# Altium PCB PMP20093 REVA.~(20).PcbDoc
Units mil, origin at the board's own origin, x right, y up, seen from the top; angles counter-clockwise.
Board outline 2600 x 2600 mil, 4 copper layers (Top Layer, Signal Layer 1, Signal Layer 2, Bottom Layer), stack 85.4 mil thick; 58 components, 27 nets, 183 pads, 90 vias.
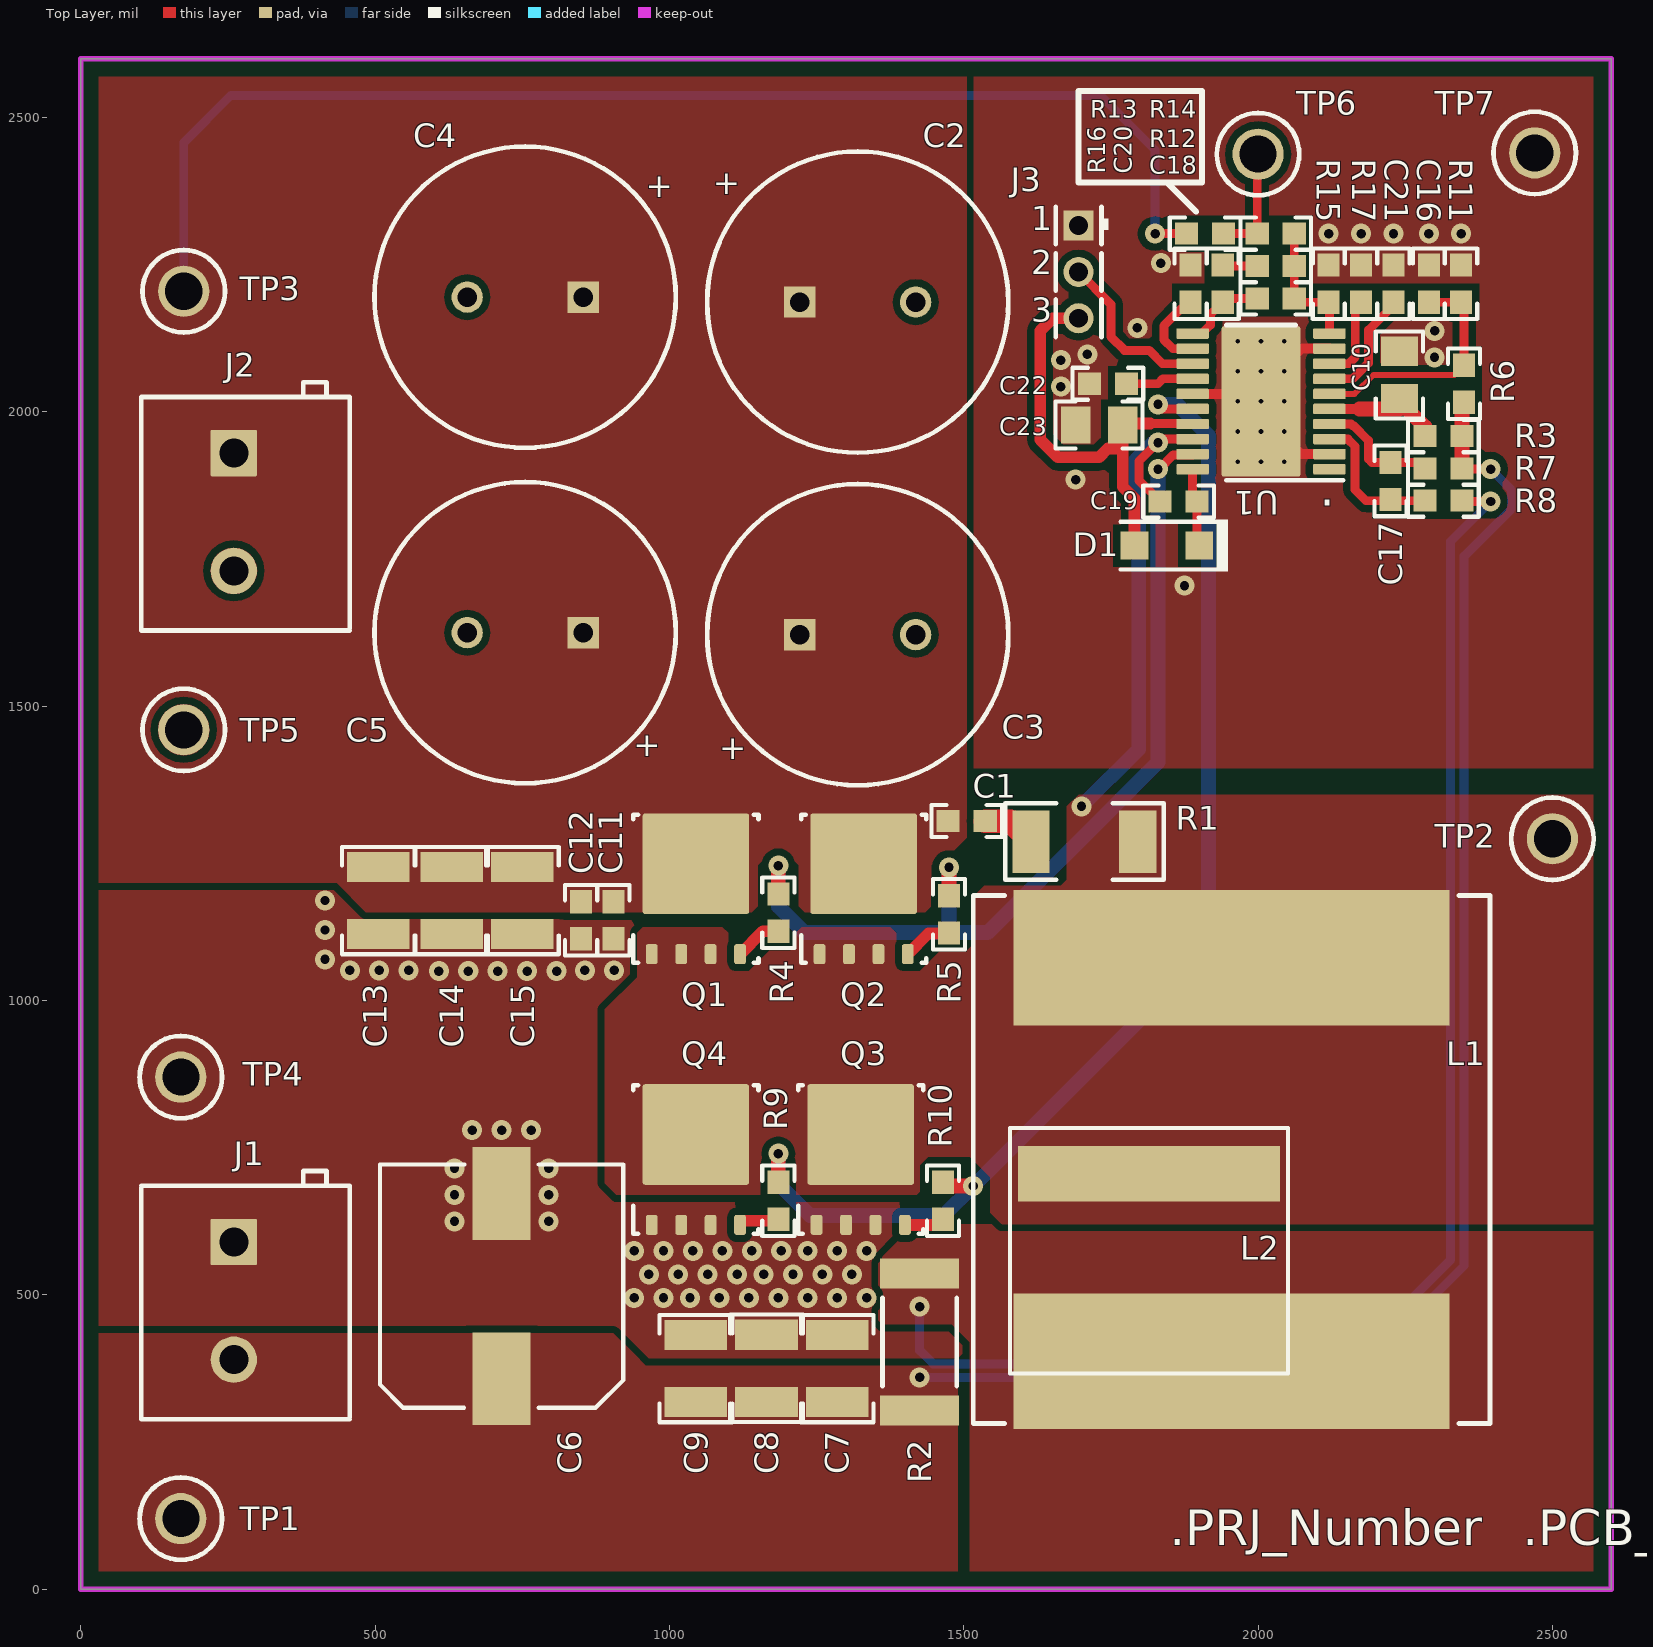
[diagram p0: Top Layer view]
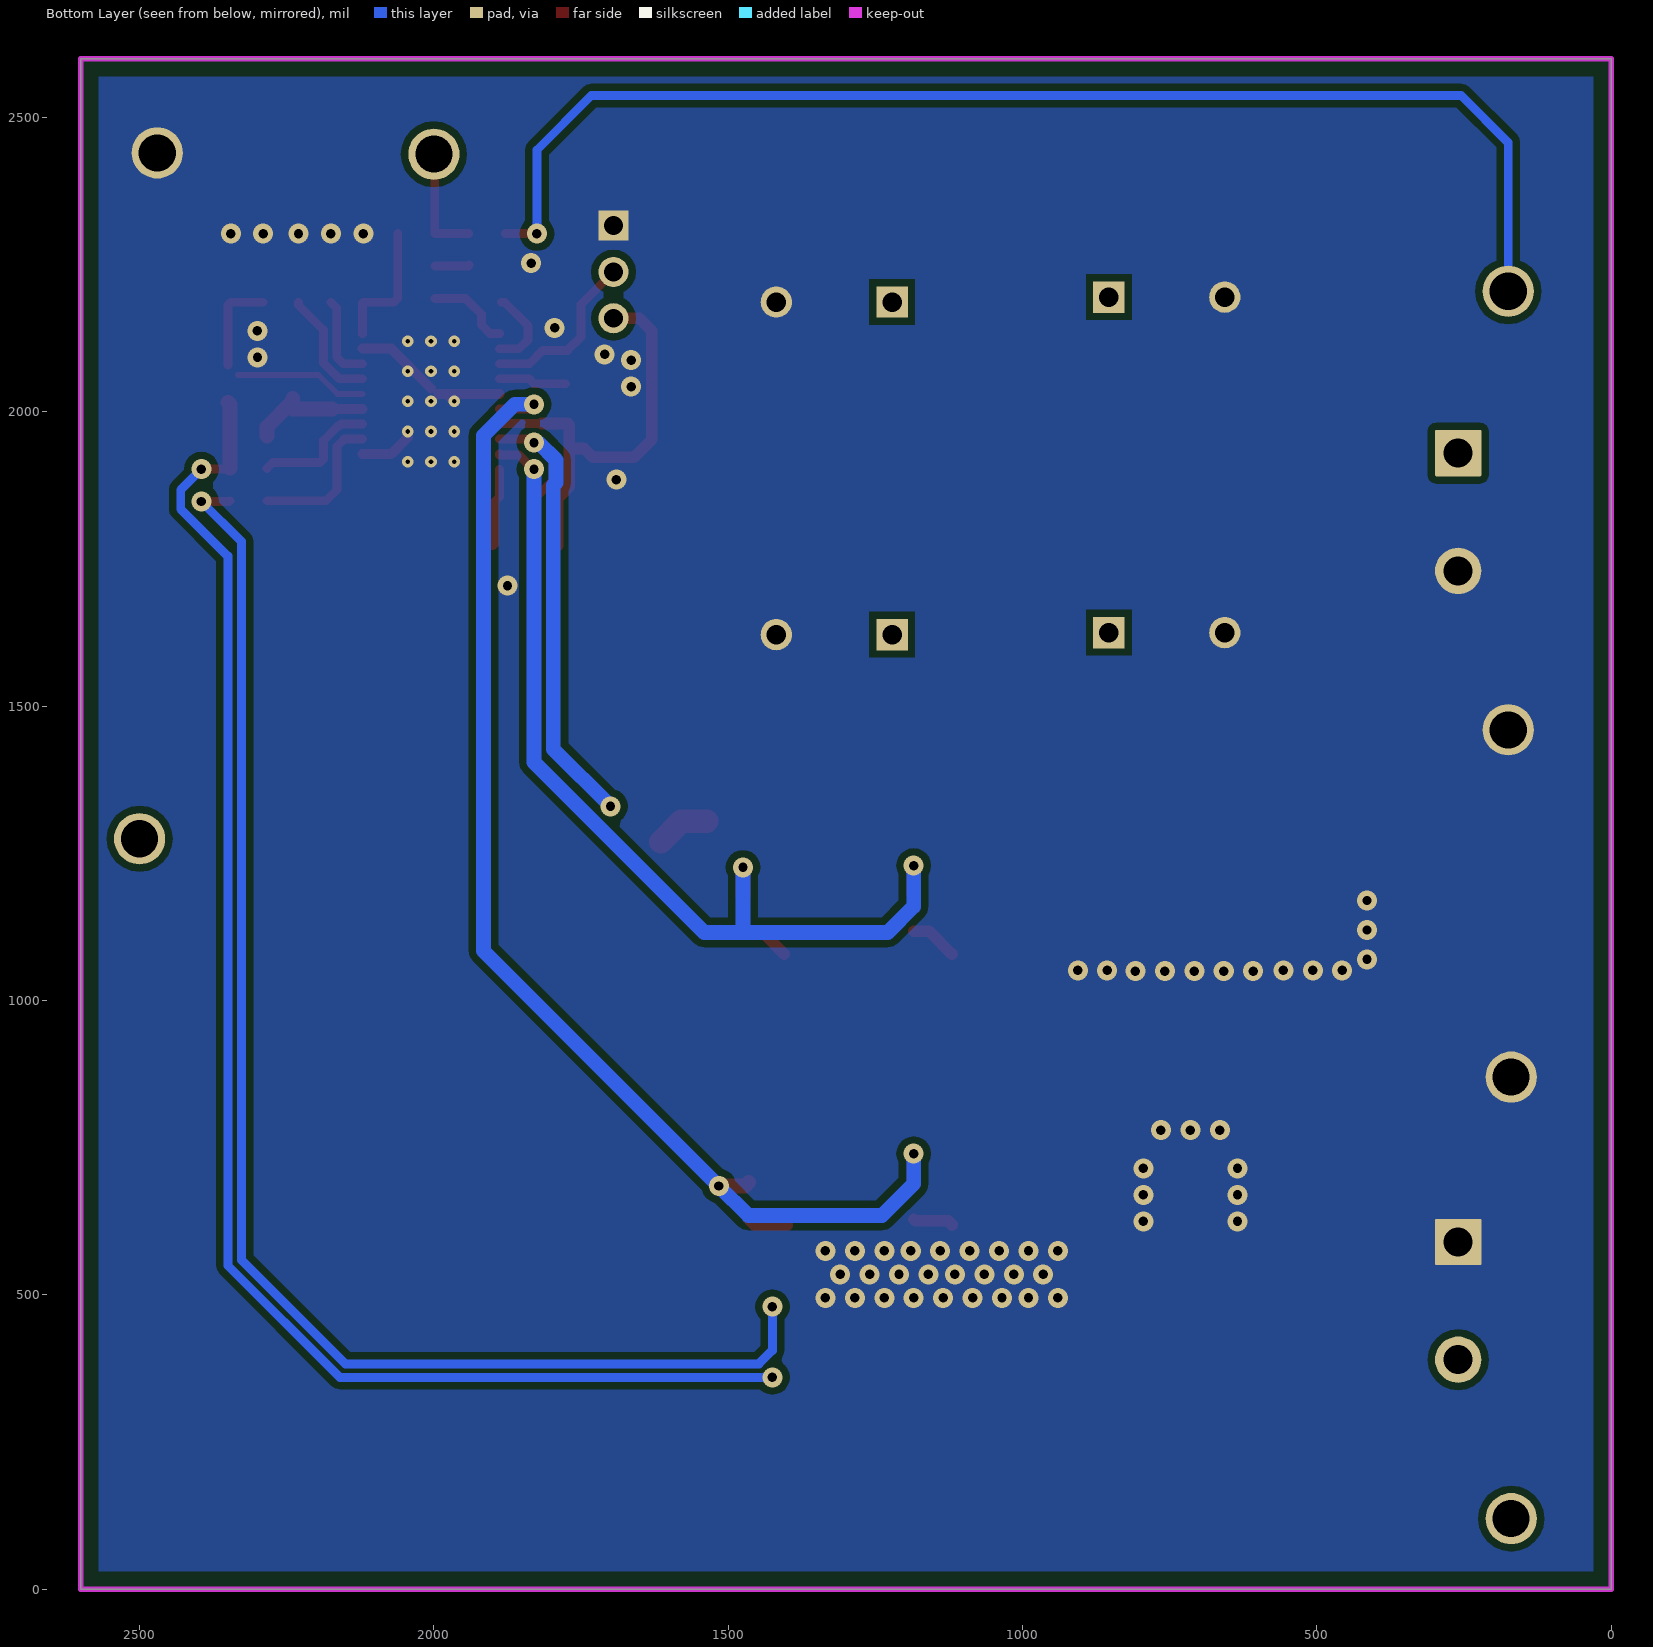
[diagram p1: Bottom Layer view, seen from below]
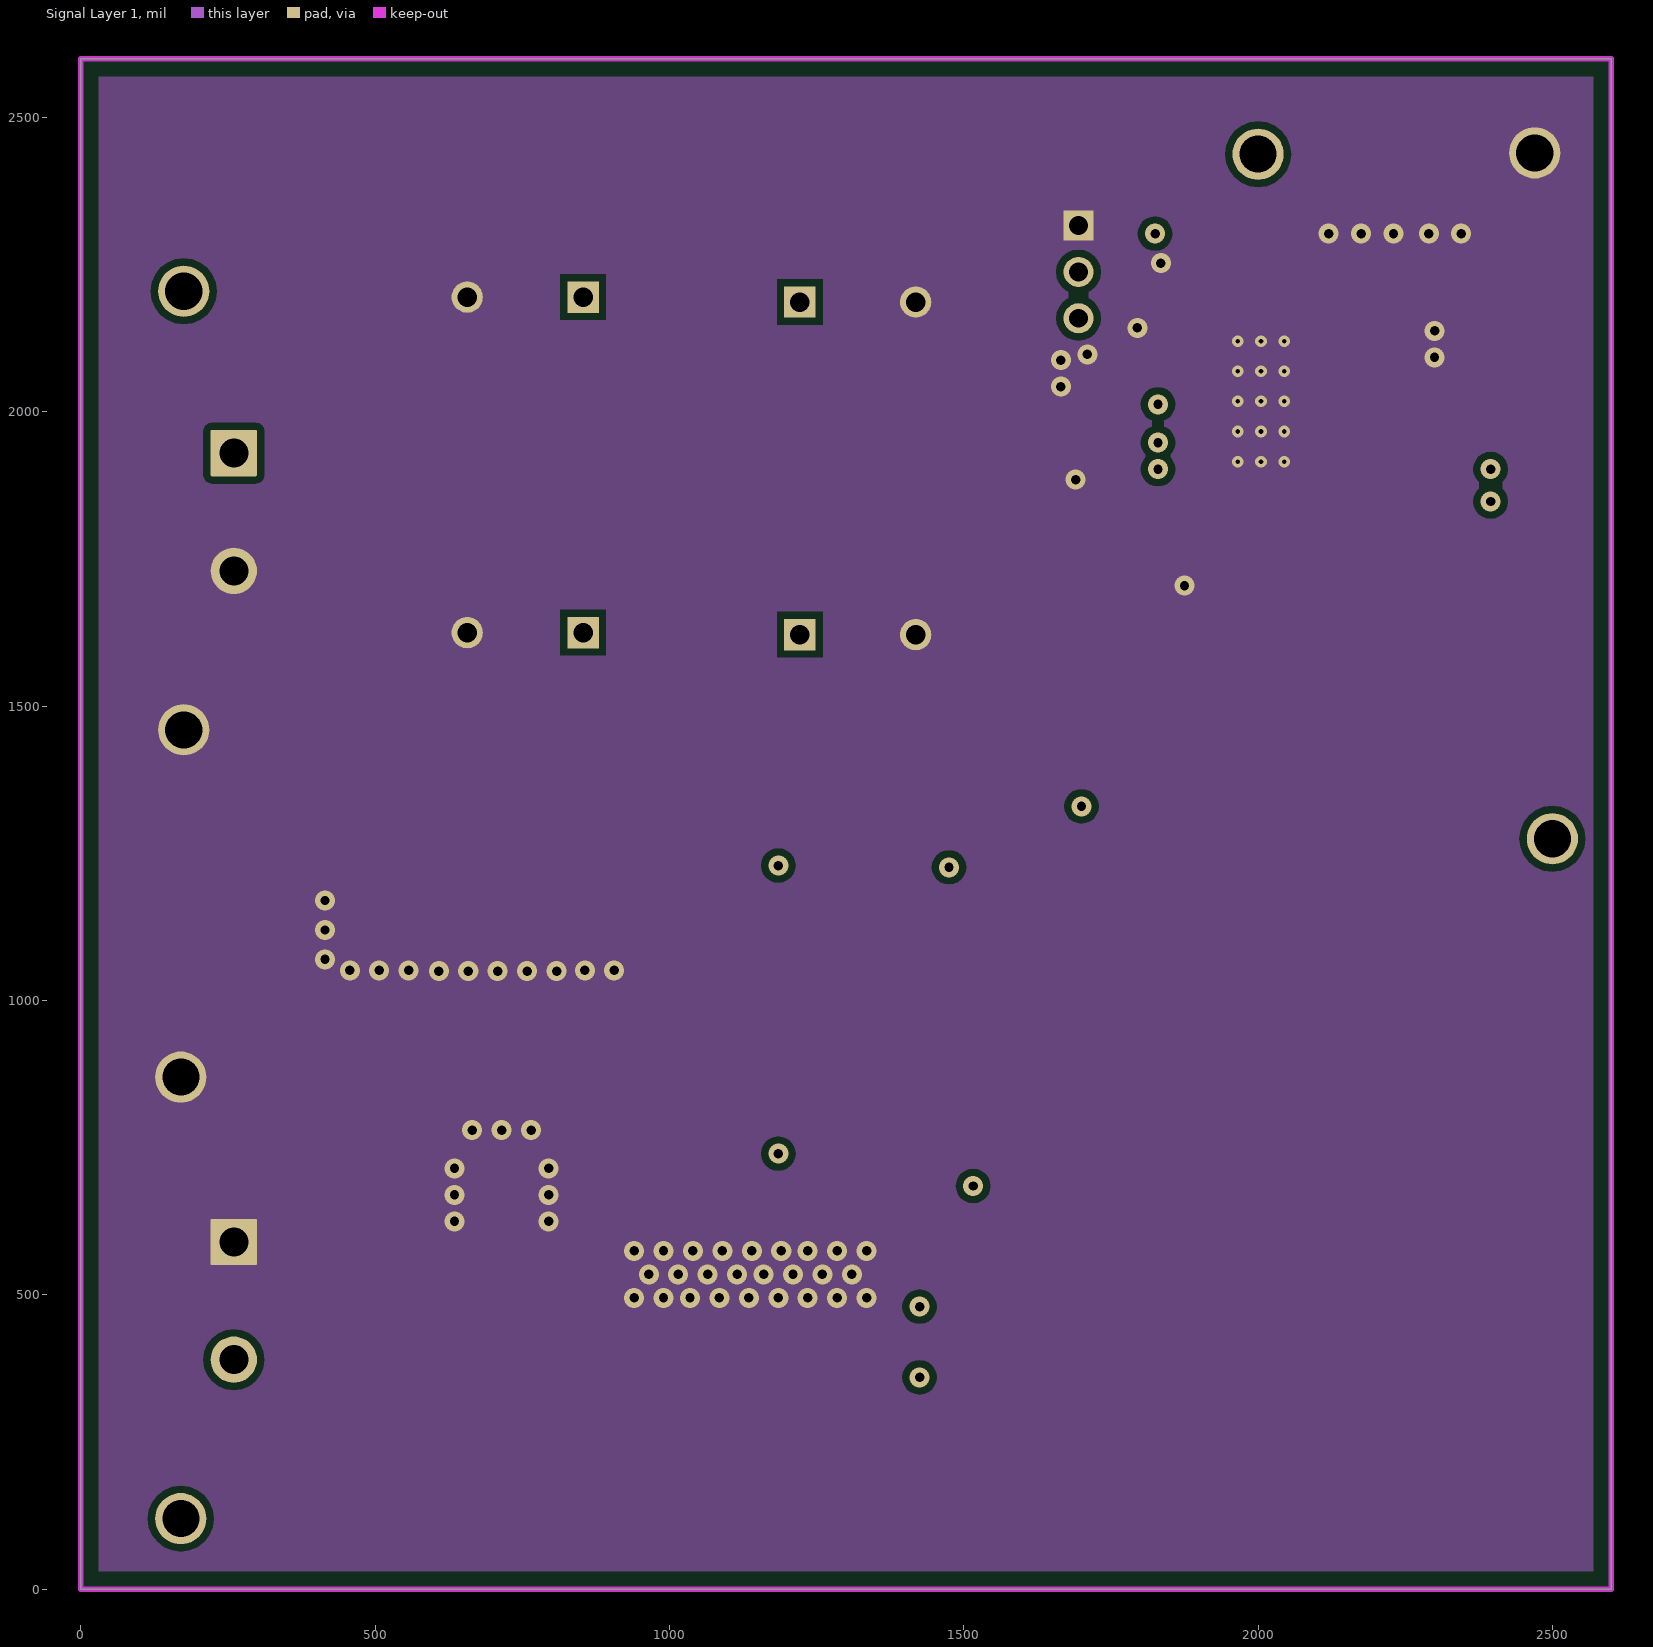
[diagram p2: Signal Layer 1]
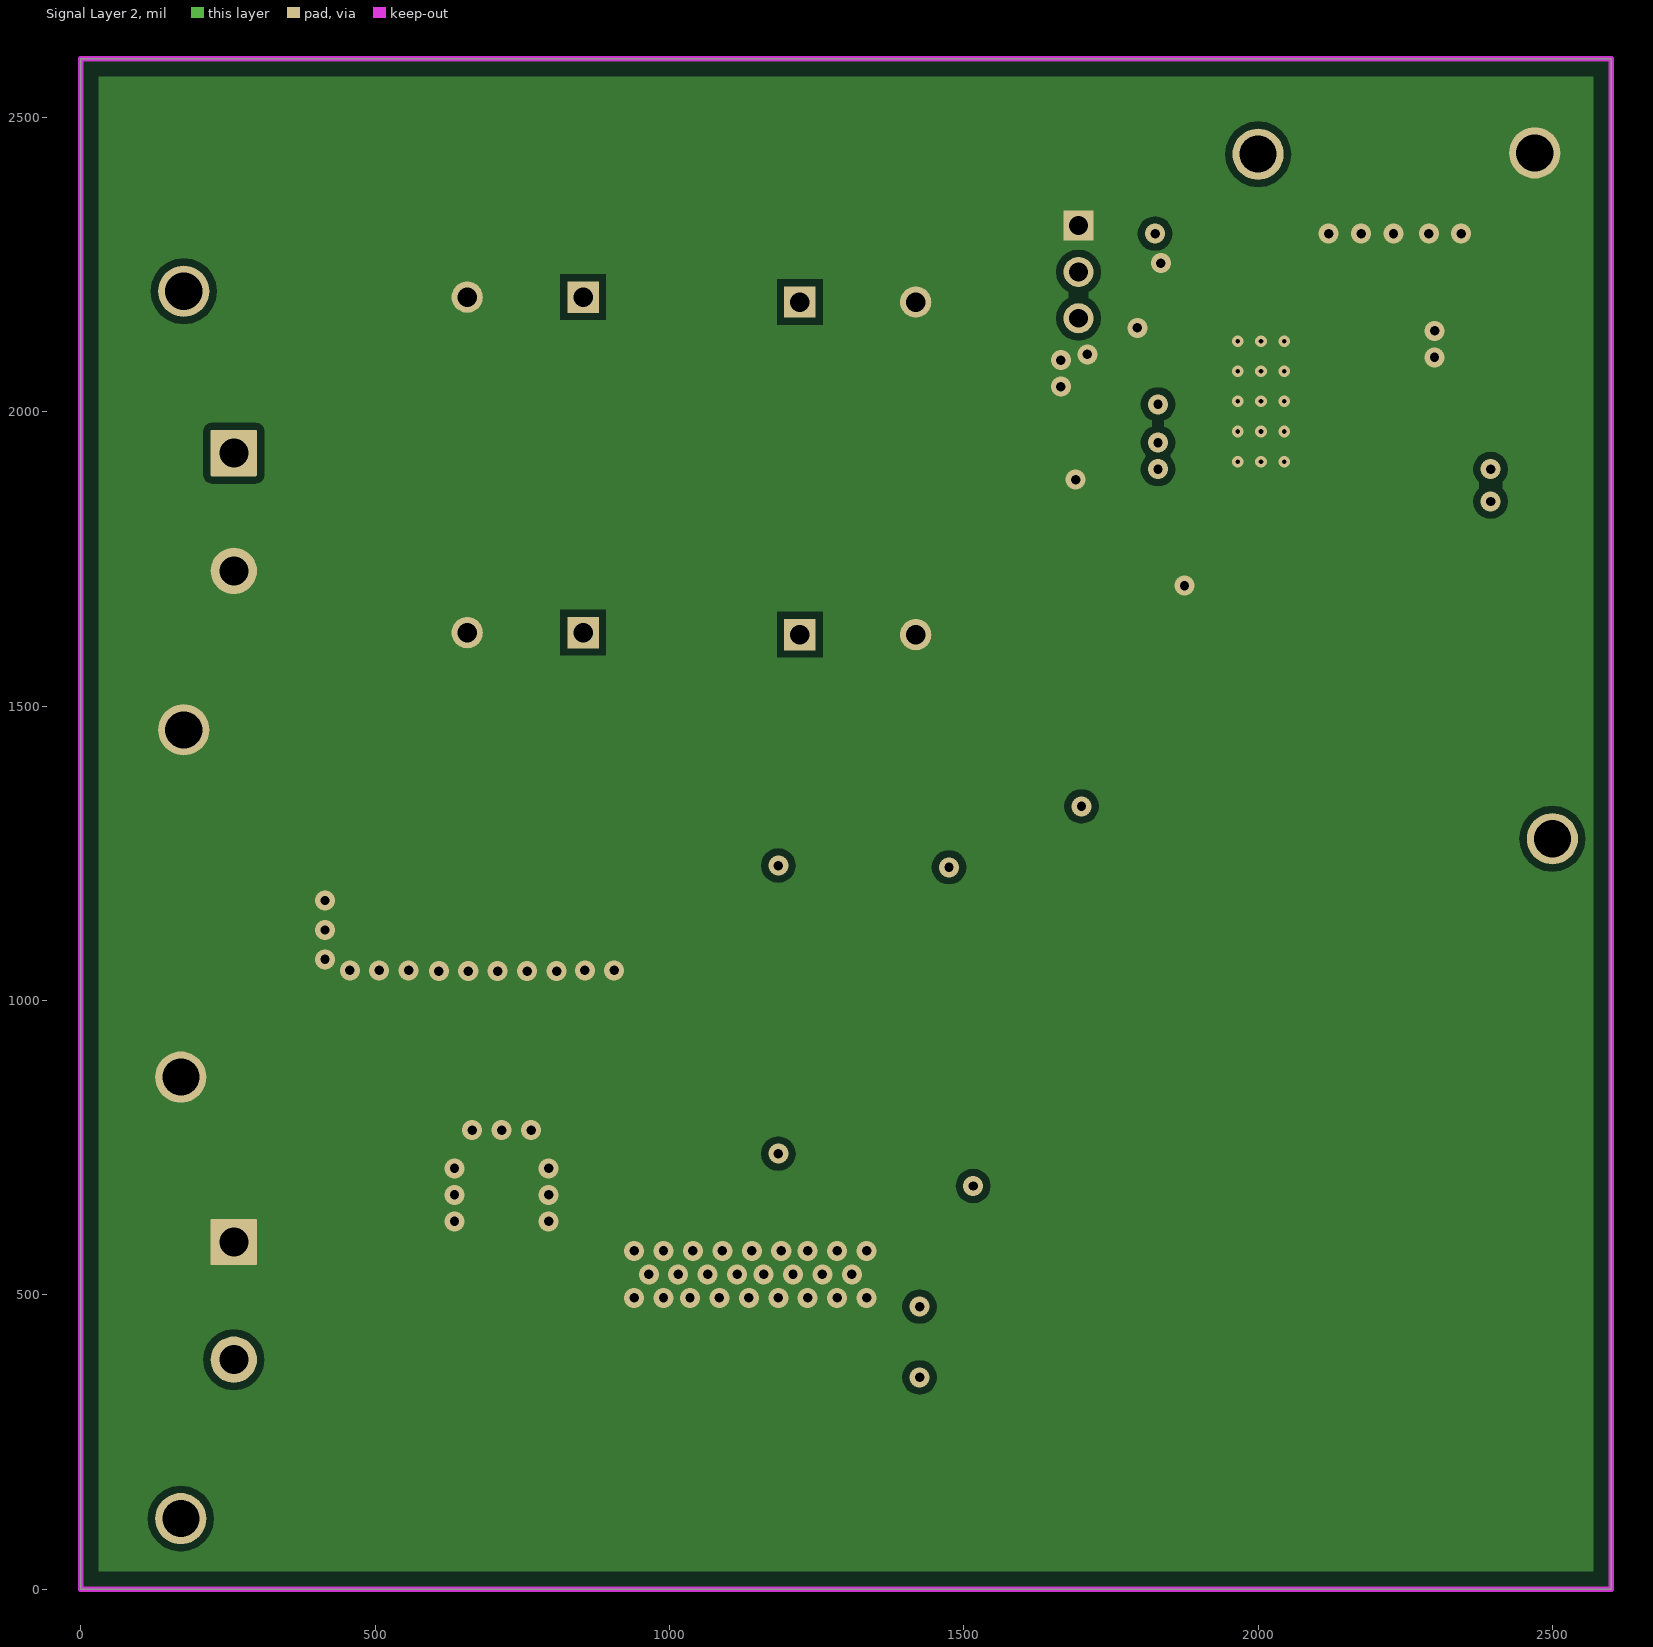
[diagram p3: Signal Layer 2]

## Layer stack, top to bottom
Top Solder: solder mask 0.4, Solder Resist, Dk 3.5
Top Layer: signal copper 2.8
Dielectric1: core 59.2, FR-4, Dk 4.8
Signal Layer 1: signal copper 2.8
Dielectric 3: prepreg 5, Dk 4.2
Signal Layer 2: signal copper 2.8
Dielectric 2: core 10, Dk 4.2
Bottom Layer: signal copper 2.8
Bottom Solder: solder mask 0.4, Solder Resist, Dk 3.5

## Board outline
0,0 2600,0 2600,2600 0,2600

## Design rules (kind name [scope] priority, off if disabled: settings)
AcuteAngle [All] p1: minimum=4.50000000000000E+0001 checktracksonly=FALSE
AssemblyTestPointUsage [All] p1: valid=2
Clearance Clearance_Keepouts [((IsTrack Or IsArc) And Not InPoly) And IsFree and IsKeepOut vs ((IsTrack Or IsArc) And Not InPoly) And IsFree and IsKeepOut] p1: gap=0
Clearance Clearance_BoardEdge_MountingHoles [OnCopper and InComponentClass('Mounting Holes') vs IsKeepOut] p2: gap=40
Clearance Clearance_BoardEdge_Poly [OnCopper and InPoly vs IsKeepOut] p3: gap=25
Clearance Clearance_BoardEdge [OnCopper and Not InComponentClass('Logo') and not InComponentClass('FiducialMark') and not InRegion(1000,500,4000,800) and Not IsKeepout vs IsKeepOut] p4: gap=50
Clearance Clearance_Poly [InPolygon] p5: gap=12
Clearance [All] p6: gap=7.87
ComponentClearance ComponentClearance_MountingHoles_FiducialMarks [InComponentClass('Mounting Holes') vs InComponentClass('FiducialMark')] p1: gap=50 collisioncheckmode=3 verticalgap=10 showdistances=FALSE
ComponentClearance ComponentClearance_Shunt [InComponentClass('Header') vs InComponentClass('Shunt')] p2: gap=0 collisioncheckmode=3 verticalgap=0 showdistances=FALSE
ComponentClearance ComponentClearance_Logo [InComponentClass('Logo')] p3: gap=50 collisioncheckmode=3 verticalgap=10 showdistances=FALSE
ComponentClearance ComponentClearance_ScrewToNut [(HasFootprint('NY PMS 440 0025 PH')) vs (HasFootprint('Keystone_1902C'))] p4: gap=5 collisioncheckmode=3 verticalgap=10 showdistances=FALSE
ComponentClearance ComponentClearance_MountingHoles [InComponentClass('Mounting Holes')] p5: gap=250 collisioncheckmode=3 verticalgap=100000 showdistances=FALSE
ComponentClearance ComponentClearance_SmallPassives [HasFootprint('0201*') or HasFootprint('0402*') or HasFootprint('0508') or HasFootprint('0603*') or HasFootprint('0612') or HasFootprint('0805*') or HasFootprint('0815*') or HasFootprint('0830*') or HasFootprint('1206*') or HasFootprint('1210*') or HasFootprint('1808*') or HasFootprint('1812*') or HasFootprint('1825*') or HasFootprint('2010*') or HasFootprint('2220*') or HasFootprint('2225*') or HasFootprint('2512*') or HasFootprint('2728*') or HasFootprint('3518*') vs HasFootprint('0201*') or HasFootprint('0402*') or HasFootprint('0508') or HasFootprint('0603*') or HasFootprint('0612') or HasFootprint('0805*') or HasFootprint('0815*') or HasFootprint('0830*') or HasFootprint('1206*') or HasFootprint('1210*') or HasFootprint('1808*') or HasFootprint('1812*') or HasFootprint('1825*') or HasFootprint('2010*') or HasFootprint('2220*') or HasFootprint('2225*') or HasFootprint('2512*') or HasFootprint('2728*') or HasFootprint('3518*')] p6: gap=12 collisioncheckmode=3 verticalgap=10 showdistances=FALSE
ComponentClearance ComponentClearance_THtoSMT [IsThruComponent vs IsSMTComponent] p7: gap=50 collisioncheckmode=3 verticalgap=30 showdistances=FALSE
ComponentClearance ComponentClearance_THtoTH [IsThruComponent vs IsThruComponent] p8: gap=50 collisioncheckmode=3 verticalgap=30 showdistances=FALSE
ComponentClearance [All] p9: gap=20 collisioncheckmode=3 verticalgap=10 showdistances=FALSE
DiffPairsRouting [All] p1: maxlimit=100 minlimit=10 mostfreqgap=10 toplayer_minwidth=15 toplayer_maxwidth=15 toplayer_prefwidth=15 midlayer1_minwidth=15 midlayer1_maxwidth=15 midlayer1_prefwidth=15 midlayer2_minwidth=15 midlayer2_maxwidth=15 midlayer2_prefwidth=15 bottomlayer_minwidth=15 bottomlayer_maxwidth=15 bottomlayer_prefwidth=15 maxuncoupledlength=1000
FabricationTestPointUsage TestPointUsage [All] p1: valid=2 allowmultiple=FALSE
FabricationTestpoint Testpoint [All] p1: side=3 testpointundercomponent=TRUE minsize=40 maxsize=100 preferedsize=60 minholesize=0 maxholesize=40 preferedholesize=32 testpointgrid=1 allowsidetop=TRUE allowsidebottom=TRUE usegrid=TRUE gridtolerance=0.01
FanoutControl Fanout_LCC [IsLCC] p1: bgadir=Out bgaviamode=Centered fanoutstyle=Auto fanoutdirection=Alternating viagrid=1 // Fanout_LCC (Default Rule)
FanoutControl Fanout_BGA [IsBGA] p2: bgadir=Out bgaviamode=Centered fanoutstyle=Auto fanoutdirection=Alternating viagrid=1 // Fanout_BGA (Default Rule)
FanoutControl Fanout_Default [All] p4: bgadir=Out bgaviamode=Centered fanoutstyle=Auto fanoutdirection=Alternating viagrid=1 // Fanout_Default (Default Rule)
FanoutControl Fanout_Small [(CompPinCount < 5)] p5: bgadir=Out bgaviamode=Centered fanoutstyle=Auto fanoutdirection=OutThenIn viagrid=1 // Fanout_Small (Default Rule)
HoleSize [All] p1: absolutevalues=TRUE maxlimit=251 minlimit=8 maxpercent=80.000 minpercent=20.000
MinimumAnnularRing MinimumAnnularRing_ThermalPadVias [IsVia and InAnyComponent] p1: minimumring=5.91
MinimumAnnularRing [All] p2: minimumring=9
MinimumSolderMaskSliver MinimumSolderMaskSliver_Logo [InComponentClass('Logo') vs InComponentClass('Logo')] p1: minsoldermaskwidth=0.7
MinimumSolderMaskSliver [All] p2: minsoldermaskwidth=3.94
PlaneClearance [All] p1: clearance=12
PlaneConnect [All] p1: planeconnectstyle=Direct reliefexpansion=10 reliefentries=4 reliefconductorwidth=10 reliefairgap=10
PolygonConnect [All] p1: connectstyle=Direct reliefconductorwidth=10 reliefentries=4 polygonreliefangle="90 Angle" airgapwidth=10
RoutingVias ThermalPadVias [IsVia and InAnyComponent] p1: holewidth=7.87 width=19.68 viastyle="Through Hole" minholewidth=7.87 minwidth=19.68 maxholewidth=12.99 maxwidth=23.62
RoutingVias [All] p2: holewidth=16 width=34 viastyle="Through Hole" minholewidth=7.87 minwidth=26 maxholewidth=40 maxwidth=65
SilkToBoardRegionClearance [Not ((IsComment or IsDesignator) And (Hide <> 'False')) and not InRegion(1000,500,4000,800)] p1:
SilkToSilkClearance SilkToSilkClearance_Pb-FreeLogo [(HasFootprint('Pb-Free_Overlay_Medium') OR HasFootprint('Pb-Free_Overlay_Small')) vs (HasFootprint('Pb-Free_Overlay_Medium') OR HasFootprint('Pb-Free_Overlay_Small'))] p1: silktosilkclearance=0
SilkToSilkClearance [All] p2: silktosilkclearance=4
SilkToSolderMaskClearance SilkToComonentPadClearance [IsPad and InAnycomponent] p1: minsilkscreentomaskgap=5 clearancetoexposedcopper=TRUE
SilkToSolderMaskClearance "Silk to Solder Mask Opening" [All] p2: minsilkscreentomaskgap=4 clearancetoexposedcopper=FALSE
SolderMaskExpansion [All] p1: expansion=1.97
Width [All] p1: maxlimit=100 minlimit=6 preferedwidth=10 checkconnectedcopper=TRUE
14 further rules are at their usual default settings.

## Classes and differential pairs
component class Header: J3

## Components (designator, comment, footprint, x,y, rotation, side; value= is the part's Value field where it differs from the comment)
C1 "C1608C0G2A471J" 0603#1 1505,1305 r0 top
C2 "50ZL680MEFC12.5X25" ZL_1250x2500 1320,2186.57 r0 top
C3 "50ZL680MEFC12.5X25" ZL_1250x2500 1320,1621.57 r0 top
C4 "50ZL680MEFC12.5X25" ZL_1250x2500 755,2195 r180 top
C5 "50ZL680MEFC12.5X25" ZL_1250x2500 755,1625 r180 top
C6 "EEHZA1V271P" SM_RADIAL_10BMM 715,515 r90 top
C7 "GRM32ER71H475KA88L" 1210_270 1285,375 r90 top
C8 "" 1210_270 1165,375.31 r90 top
C9 "" 1210_270 1045,375 r90 top
C10 "C2012X7R1H105K125AB" 0805_HV 2240,2062.87 r270 top
C11 "C1608C0G2A471J" 0603#1 905,1136.5 r270 top
C12 "C1608X7R1H104K080AA" 0603#1 850,1136.5 r90 top
C13 "GRM32ER71H475KA88L" 1210_270 505.32,1170 r270 top
C14 "GRM32ER71H475KA88L" 1210_270 630.32,1170 r270 top
C15 "GRM32ER71H475KA88L" 1210_270 750.32,1170 r270 top
C16 "GRM188R71H102KA01D" 0603#1 2290,2217.87 r90 top
C17 "C1608C0G2A471J" 0603#2 2193.7,1816.57 r270 top
C18 "GRM1885C1H680JA01D" 0603#1 2030,2192.87 r0 top
C19 "GRM188R71E474KA12D" 0603#1 1865,1847.87 r0 top
C20 "GRM188R71H333KA61D" 0603#1 1940,2217.87 r90 top
C21 "C1608X7R1E105K080AB" 0603#1 2230,2217.87 r90 top
C22 "GRM188R71E474KA12D" 0603#1 1745,2047.87 r0 top
C23 "GRM21BZ71E106KE15L" 0805_HV 1730,1977.87 r180 top
D1 "PMEG6010CEH" SOD-123F 1845,1772.87 r180 top
J1 "ED120/2DS" On-Shore_ED120_2DS 260,490 r270 top
J2 "ED120/2DS" On-Shore_ED120_2DS 260,1830 r270 top
J3 "PTT-103-01-L-S" Samtec_PTT-103-01-x-S 1695,2237.87 r270 top
L1 "IHLP8787MZER6R8M5A" IHLP8787MZ 1955,730 r90 top
L2 "" XAL1010 1815,575 r90 top
Q1 "" DNK0008A#1 1045,1270 r90 top
Q2 "CSD18532Q5B" DNK0008A#2 1280,1335 r90 top
Q3 "CSD18532Q5B" DNK0008A#3 1325,730 r90 top
Q4 "CSD18532Q5B" DNK0008A#3 1045,730 r90 top
R1 "CRM2010-JW-7R5ELF" 2010 1705,1270 r180 top
R2 "CSNL2512FT2L00" 2512 1425,420 r90 top
R3 "CRCW06033R30JNEA" 0603#1 2315,1959.17 r0 top
R4 "CRCW06030000Z0EA" 0603#1 1185,1149.43 r270 top
R5 "CRCW06030000Z0EA" 0603#1 1475,1146.5 r270 top
R6 "CRCW060349K9FKEA" 0603#1 2349.68,2047.87 r270 top
R7 "CRCW0603100RFKEA" 0603#1 2315,1904.17 r180 top
R8 "CRCW0603100RFKEA" 0603#1 2315,1849.17 r180 top
R9 "CRCW06030000Z0EA" 0603#1 1185,660 r90 top
R10 "CRCW06030000Z0EA" 0603#1 1465,660 r270 top
R11 "CRCW06037K87FKEA" 0603#1 2345,2217.87 r270 top
R12 "CRCW0603158KFKEA" 0603#1 2030,2247.87 r180 top
R13 "CRCW0603100RFKEA" 0603#1 1910,2302.87 r180 top
R14 "CRCW060349K9FKEA" 0603#1 2030,2302.87 r180 top
R15 "CRCW06031K78FKEA" 0603#1 2120,2217.87 r270 top
R16 "CRCW060335K7FKEA" 0603#1 1885,2217.87 r270 top
R17 "CRCW060335K7FKEA" 0603#1 2175,2217.87 r270 top
TP1 "5010" Keystone5010 170,120 r0 top
TP2 "5010" Keystone5010 2500,1275 r0 top
TP3 "5010" Keystone5010 175,2205 r0 top
TP4 "5011" Keystone5011 170,870 r0 top
TP5 "5011" Keystone5011 175,1460 r0 top
TP6 "5010" Keystone5010 2000,2437.87 r180 top
TP7 "5011" Keystone5011 2470,2440 r180 top
U1 "LM5122MHX/NOPB" PWP0020A_N 2005,2017.87 r180 top

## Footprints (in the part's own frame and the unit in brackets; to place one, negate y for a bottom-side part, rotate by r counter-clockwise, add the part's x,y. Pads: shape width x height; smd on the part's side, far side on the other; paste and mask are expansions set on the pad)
0603#1 [mm] "0603 from SM-752 data"
  rect 1x0.95 smd: 1(-0.8,0) 2(0.8,0)
  silkscreen extent -1.52,-0.69 1.52,0.69, body extent -0.87,-0.47 0.87,0.47, height 1
0603#2 [mm] "0603 from SM-752 data"
  rect 1x0.95 smd: 1(-2.484,0.795) 2(-0.884,0.795)
  silkscreen extent -3.21,0.1 -0.16,1.49, body extent -2.56,0.32 -0.81,1.27, height 1
0805_HV [mil] "0805 with 30mil clearance between pads"
  rect 50x63 smd: 1(-40,0) 2(40,0)
  silkscreen extent -74,-40 74,40, body extent -43,-29 43,29, height 57
1210_270 [mm] "1210"
  rect 1.3x2.7 smd: 1(-1.45,0) 2(1.45,0)
  silkscreen extent -2.32,-1.57 2.32,1.57, body extent -1.7,-1.35 1.7,1.35, height 2.7
2010 [mm] "Chip Capacitor, Body 5.08x2.54mm, IPC Medium Density"
  rect 1.6x2.7 smd: 1(-2.3,0) 2(2.3,0)
  silkscreen extent -3.42,-1.65 3.42,1.65, body extent -2.73,-1.45 2.73,1.45, height 1.66
2512 [mm] "Chip Resistor, Body 6.3x3.2mm, IPC Medium Density"
  rect 1.3x3.4 smd: 1(-2.95,0) 2(2.95,0)
  silkscreen extent -1.9,-1.6 1.9,1.6, body extent -3.22,-1.67 3.22,1.67, height 0.71
DNK0008A#1 [mm] "SON, 8-Leads, Body 5x6mm"
  rrect39% 0.86x0.51 smd paste-0.05 mask-0.05: 1(-4.852,1.905) 2(-4.852,0.635) 3(-4.852,-0.635) 4(-4.852,-1.905) 5(0.788,-1.905) 6(0.788,-0.635) 7(0.788,0.635) 8(0.788,1.905)
  rrect8% 1.48x1.27 on Top Paste: 9(-2.212,-1.47) 9(-2.212,0) 9(-2.212,1.47) 9(-0.532,1.47) 9(-0.532,0) 9(-0.532,-1.47)
  rrect5% 4.34x4.6 smd paste-3 mask-0.05: 9(-0.952,0)
  silkscreen extent -5.23,-2.7 1.17,2.7, body extent -5.08,-2.55 1.02,2.55, height 1.06
DNK0008A#2 [mm] "SON, 8-Leads, Body 5x6mm"
  rrect39% 0.86x0.51 smd paste-0.05 mask-0.05: 1(-6.503,0.635) 2(-6.503,-0.635) 3(-6.503,-1.905) 4(-6.503,-3.175) 5(-0.863,-3.175) 6(-0.863,-1.905) 7(-0.863,-0.635) 8(-0.863,0.635)
  rrect8% 1.48x1.27 on Top Paste: 9(-3.863,-2.74) 9(-3.863,-1.27) 9(-3.863,0.2) 9(-2.183,-2.74) 9(-2.183,-1.27) 9(-2.183,0.2)
  rrect5% 4.34x4.6 smd paste-3 mask-0.05: 9(-2.603,-1.27)
  silkscreen extent -6.88,-3.97 -0.48,1.43, body extent -6.73,-3.82 -0.63,1.28, height 1.06
DNK0008A#3 [mm] "SON, 8-Leads, Body 5x6mm"
  rrect39% 0.86x0.51 smd paste-0.05 mask-0.05: 1(-2.82,1.905) 2(-2.82,0.635) 3(-2.82,-0.635) 4(-2.82,-1.905) 5(2.82,-1.905) 6(2.82,-0.635) 7(2.82,0.635) 8(2.82,1.905)
  rrect8% 1.48x1.27 on Top Paste: 9(-0.18,1.47) 9(-0.18,0) 9(-0.18,-1.47) 9(1.5,-1.47) 9(1.5,0) 9(1.5,1.47)
  rrect5% 4.34x4.6 smd paste-3 mask-0.05: 9(1.08,0)
  silkscreen extent -3.2,-2.7 3.2,2.7, body extent -3.05,-2.55 3.05,2.55, height 1.06
IHLP8787MZ [mm] "SMD, 2-Leads, Body 22x22.48mm"
  rect 5.84x18.8 smd: 1(-8.7,0) 2(8.7,0)
  silkscreen extent -11.39,-11.15 11.39,11.15, body extent -11.39,-11.15 11.39,11.15, height 13
Keystone5010 [mil] "Keystone Multipurpose loops"
  round 87 hole 63: 1(0,0)
  silkscreen extent -70,-70 70,70, body extent -63,-63 63,62, height 319
Keystone5011 [mil] "Keystone Multipurpose loops"
  round 87 hole 63: 1(0,0)
  silkscreen extent -70,-70 70,70, body extent -63,-63 63,62, height 319
On-Shore_ED120_2DS [mm] "ONSHORE"
  rrect5% 2x2 hole 1.25: 1(-2.54,0)
  round 2 hole 1.25: 2(2.54,0)
  silkscreen extent -5.6,-4 5.12,5, body extent -5.78,-4 5.08,5, height 13
PWP0020A_N [mm] "TSOP, 20-Leads, Body 6.5x4.4mm, Pitch 0.65mm, Exposed Pad, IPC Medium Density"
  rrect22% 1.4x0.45 smd: 1(-2.95,2.925) 2(-2.95,2.275) 3(-2.95,1.625) 4(-2.95,0.975) 5(-2.95,0.325) 6(-2.95,-0.325) 7(-2.95,-0.975) 8(-2.95,-1.625) 9(-2.95,-2.275) 10(-2.95,-2.925) 11(2.95,-2.925) 12(2.95,-2.275) 13(2.95,-1.625) 14(2.95,-0.975) 15(2.95,-0.325) 16(2.95,0.325) 17(2.95,0.975) 18(2.95,1.625) 19(2.95,2.275) 20(2.95,2.925)
  rrect6% 3.4x6.5 smd paste-2 mask-2: 21(0,0)
  rrect3% 3.15x4.35 on Top Paste: 21(0,0)
  rrect3% 3.15x4.35 on Top Solder: 21(0,0)
  silkscreen extent -3.55,-3.3 1.5,3.4, body extent -3.21,-3.25 3.21,3.25, height 1
Samtec_PTT-103-01-x-S [mm] "Header, 2mm, 3x1, TH"
  rect 1.3x1.3 hole 0.81: 1(-2,0)
  round 1.3 hole 0.81: 2(0,0) 3(2,0)
  silkscreen extent -2.81,-0.99 2.81,1.3, body extent -3,-0.99 3,0.99, height 4.7
SM_RADIAL_10BMM [mm] "Nichicon 10x10"
  rect 4x2.5 smd: 1(-4,0) 2(4,0)
  silkscreen extent -5.25,-5.25 5.25,5.25, body extent -5.25,-5.25 5.25,5.25, height 10.5
SOD-123F [mm] "NXP recommended land pattern"
  rect 1.2x1.2 smd paste-0.05: 1(-1.4,0) 2(1.4,0)
  silkscreen extent -2.64,-1.12 2.01,1.12, body extent -1.8,-0.85 1.8,0.85, height 1.2
XAL1010 [mm] "COILCRAFT"
  rect 2.38x11.31 smd: 1(-3.325,0) 2(3.325,0)
  silkscreen extent -5.3,-6 5.3,6, body extent -5.25,-5.9 5.25,5.9, height 10
ZL_1250x2500 [mm] "TH, 2-Leads, Dia 12.5mm, Lead Spacing 5mm"
  rect 1.35x1.35 hole 0.85: 1(-2.5,0)
  round 1.35 hole 0.85: 2(2.5,0)
  silkscreen extent -6.5,-6.5 6.5,6.5, body extent -6.45,-6.49 6.49,6.49, height 27.01

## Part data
C1 C11 C17: "CAP, CERM, 470 pF, 100 V, +/- 5%, C0G/NP0, 0603"
C2 C3 C4 C5: library part 50ZL560MEFC12.5X25, "CAP, AL, 680 µF, 50 V, +/- 20%, 2.86A, 0.021 ohm, TH"
C6: "CAP, Polymer Hybrid, 270 µF, 35 V, +/- 20%, 20 ohm, 10x10 SMD"
C7 C13 C14 C15: "CAP, CERM, 4.7 µF, 50 V, +/- 10%, X7R, 1210"
C8 C9: library part GRM32ER71H475KA88L, "CAP, CERM, 1210"
C10: "CAP, CERM, 1 µF, 50 V, +/- 10%, X7R, 0805"
C12: "CAP, CERM, 0.1 µF, 50 V, +/- 10%, X7R, 0603"
C16: "CAP, CERM, 1000pF, 50V, +/-10%, X7R, 0603"
C18: "CAP, CERM, 68 pF, 50 V, +/- 5%, C0G/NP0, 0603"
C19 C22: "CAP, CERM, 0.47uF, 25V, +/-10%, X7R, 0603"
C20: "CAP, CERM, 0.033 µF, 50 V, +/- 10%, X7R, 0603"
C21: "CAP, CERM, 1 µF, 25 V, +/- 10%, X7R, 0603"
C23: "CAP, CERM, 10 µF, 25 V, +/- 10%, X7R, 0805"
D1: library part PMEG6010CEH,115, "Diode, Schottky, 60V, 1A, SOD-123F"
J1 J2: "Terminal Block, 5.08 mm, 2x1, Brass, TH"
J3: "Header, 2mm, 3x1, Gold, TH"
L1: library part IHLP8787MZER100M5A, "Inductor, Shielded, 6.8 µH, 36A, 0.00284 ohm, AEC-Q200 Grade 0, SMD"
L2: library part XAL1010-222MEB, "Inductor, SMD, alternate footprint"
Q1: library part CSD18532Q5B, "MOSFET, N-CH, DNP"
Q2 Q3 Q4: "MOSFET, N-CH, 60 V, 172 A, DNK0008A (VSON-CLIP-8)"
R1: "RES, 7.5, 5%, 1 W, 2010"
R2: "RES, 0.002, 1%, 2 W, 2512"
R3: "RES, 3.3 ohm, 5%, 0.1W, 0603"
R4 R5 R9 R10: "RES, 0, 5%, 0.1 W, 0603"
R6 R14: "RES, 49.9k ohm, 1%, 0.1W, 0603"
R7 R8: "RES, 100, 1%, 0.1 W, 0603"
R11: "RES, 7.87 k, 1%, 0.1 W, 0603"
R12: "RES, 158 k, 1%, 0.1 W, 0603"
R13: "RES, 100 ohm, 1%, 0.1W, 0603"
R15: "RES, 1.78 k, 1%, 0.1 W, 0603"
R16 R17: "RES, 35.7 k, 1%, 0.1 W, 0603"
TP1 TP2 TP3 TP6: "Test Point, Multipurpose, Red, TH"
TP4 TP5 TP7: "Test Point, Multipurpose, Black, TH"
U1: "Wide Input Synchronous Boost Controller with Multiple Phase Capability, PWP0020A (TSSOP-20)"

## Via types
v1: diameter 34, hole 16, Top Layer to Bottom Layer, 75 vias
v2: diameter 19.68, hole 7.87, Top Layer to Bottom Layer, 9 vias
v3: diameter 19.68, hole 7.87, Top Layer to Bottom Layer, tented both sides, 6 vias

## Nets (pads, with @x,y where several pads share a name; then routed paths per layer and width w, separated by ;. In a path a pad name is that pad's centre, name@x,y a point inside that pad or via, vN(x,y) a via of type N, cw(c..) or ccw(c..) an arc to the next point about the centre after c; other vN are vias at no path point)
GND: C2.2 C3.2 C4.2 C5.2 C6.2 C7.2 C8.2 C9.2 C10.1 C11.2 C12.1 C13.2 C14.2 C15.2 C16.2 C21.2 C22.1 C23.2 J1.1 J2.2 J3.1 Q3.1 Q3.2 Q3.3 Q4.1 Q4.2 Q4.3 R11.1 R15.1 R16.1 R17.1 TP4.1 TP5.1 TP7.1 U1.2 U1.9 U1.15 U1.21@2005,2017.87 | length 364.2
  Top Layer w17: U1.15 U1.21@1978.43,2030.66 ; v2(1965.63,2017.87) U1.21@1978.43,2030.66 ; U1.21@1992.2,2030.66 U1.21@1978.43,2030.66 ; U1.21@2005,2040 2072.43,2107.43 U1.9 ; v2(2044.37,1966.69) 2044.37,1956.5 2072.57,1928.3 U1.2
  other v1: 940,495 990,495 1035,495 1085,495 1135,495 1185,495 1235,495 1285,495 1335,495 965,535 1015,535 1065,535 1115,535 1160,535 1210,535 1260,535 1310,535 940,575 990,575 1040,575 1090,575 1140,575 1190,575 1235,575 1285,575 1335,575 635,625 795,625 635,670 795,670 635,715 795,715 665,780 715,780 765,780 608.31,1050 658.31,1050 708.31,1050 758.31,1050 808.31,1050 457.04,1051.32 507.04,1051.32 557.04,1051.32 856.3,1051.5 906.3,1051.5 415,1070 415,1120 415,1170 1875,1705 1690,1885 1665,2042.87 1665,2087.87 2299.68,2092.87 1710,2097.87 2300,2137.87 1795,2142.87 1835,2252.87 2120,2302.87 2175,2302.87 2230,2302.87 2290,2302.87 2345,2302.87
  other v2: 1965.63,1966.69 2005,1966.69 2005,2017.87 2044.37,2017.87 1965.63,2069.05 2005,2069.05 2044.37,2069.05
  other v3: 1965.63,1915.5 2005,1915.5 2044.37,1915.5 1965.63,2120.23 2005,2120.23 2044.37,2120.23
NetC1_2: C1.2 R1.2 | length 92.5
  Top Layer w40: C1.2 1579.45,1305 R1.2
NetC6_1: C6.1 C7.1 C8.1 C9.1 J1.2 R2.1 R3.2 R6.2 R7.1 TP1.1 | length 2566.8
  Top Layer w15: R7.1 2347.8,1902.87 v1(2395,1902.87)
  Top Layer w25: R7.1 R3.2 2346.5,2013.18 R6.2
  Bottom Layer w15: v1(1425,360) 2160,360 2350,550 2350,1755 2430,1835 2430,1867.87 v1(2395,1902.87)
NetC10_2: C10.2 R3.1 U1.5 | length 200.6
  Top Layer w17: U1.5 2172.2,2005.07
  Top Layer w25: 2172.2,2005.07 C10.2@2240,2005.07 ; C10.2 2240,2018.55 2283.5,1975.05 R3.1
NetC16_1: C16.1 R6.1 R11.2 U1.6 | length 389.3
  Top Layer w10: U1.6 2163.96,2030.66 2196.16,2062.87 R6.1@2333.19,2062.87
  Top Layer w15: C16.1 R11.2 2349.68,2181.69 R6.1
NetC17_1: C17.1 R7.2 U1.4 | length 211.9
  Top Layer w15: U1.4 2158.38,1979.48 2160.66,1977.2 2161.61,1977.2 2187.56,1951.25 2187.56,1919.99 2193.19,1914.36 C17.1 2273.31,1914.36 R7.2
NetC17_2: C17.2 R8.2 U1.3 | length 249
  Top Layer w15: U1.3 2152.57,1953.89 2164.68,1941.77 2164.68,1867.87 2183.39,1849.17 R8.2
NetC18_1: C18.1 C20.1 U1.11 | length 144.9
  Top Layer w15: U1.11 1904.49,2133.02 1919.07,2147.61 1919.07,2165.44 C20.1 1946.5,2192.87 C18.1
NetC18_2: C18.2 R12.1 R14.1 R15.2 U1.10 | length 223.4
  Top Layer w15: R14.1 R12.1 C18.2 2067.99,2186.37 R15.2 ; U1.10 R15.2@2121.14,2185.23
NetC19_1: C19.1 L1.2 L2.2 Q1.1 Q1.2 Q1.3 Q2.1 Q2.2 Q2.3 Q3.5 Q3.6 Q3.7 Q3.8 Q3.9@1325,772.52 Q4.5 Q4.6 Q4.7 Q4.8 Q4.9@1045,772.52 R1.1 TP2.1 U1.18 | length 870.1
  Top Layer w15: C19.1 1797.63,1883.74 1797.63,1916.28 1829.22,1947.87 v1(1830,1947.87) 1836.02,1953.89 U1.18
  Bottom Layer w25: v1(1700,1330) 1797.13,1427.13 1797.13,1875.13 1792.63,1879.63 1792.63,1918.35 1822.15,1947.87 v1(1830,1947.87)
NetC19_2: C19.2 D1.1 U1.20 | length 134.5
  Top Layer w15: U1.20 1888.86,1855.5 C19.2 1896.5,1776.49 D1.1
NetC20_2: C20.2 R12.2 | length 59.1
  Top Layer w15: C20.2 1941.5,2247.87 R12.2
NetC21_1: C21.1 U1.7 | length 198.4
  Top Layer w15: U1.7 2160.73,2056.25 2187.87,2083.39 2187.87,2139.12 2230,2181.24 C21.1
NetC22_2: C22.2 U1.14 | length 115.8
  Top Layer w15: C22.2 1830,2047.87 1838.39,2056.25 U1.14
NetJ3_2: J3.2 U1.13 | length 290.7
  Top Layer w15: J3.2 1750,2182.87 1750,2127.87 1773.31,2104.56 1815,2104.56 1837.72,2081.84 U1.13
NetL1_1: L1.1 L2.1 R2.2 R8.1 | length 2424.5
  Top Layer w15: R8.1 2347.8,1847.87 v1(2395,1847.87)
  Bottom Layer w15: v1(1425,480) 1425,405.78 1447.91,382.87 2150.53,382.87 2327.13,559.47 2327.13,1779.99 v1(2395,1847.87)
NetQ1_4: Q1.4 R4.2 | length 81.1
  Top Layer w20: Q1.4 1158.96,1117.93 R4.2
NetQ2_4: Q2.4 R5.2 | length 84.9
  Top Layer w20: Q2.4 1440,1113.98 1473.98,1113.98 R5.2
NetQ3_4: Q3.4 R10.2 | length 68.9
  Top Layer w20: Q3.4 1455.47,618.98 R10.2
NetQ4_4: Q4.4 R9.1 | length 69.5
  Top Layer w20: Q4.4 1120,620 1126,626 1182.5,626 R9.1
NetR4_1: R4.1 R5.1 U1.19 | length 1628.5
  Top Layer w15: v1(1830,1902.87) 1832,1902.87 1856.07,1926.94 1888.86,1926.94 U1.19
  Top Layer w25: R4.1 v1(1185,1229.43) ; R5.1 v1(1475,1226.5)
  Bottom Layer w25: v1(1185,1229.43) 1185,1160 1229.3,1115.7 1540.7,1115.7 1830,1405 v1(1830,1902.87) ; 1475,1115.7 v1(1475,1226.5)
NetR9_2: R9.2 R10.1 U1.16 | length 2137.9
  Top Layer w15: v1(1830,2012.87) 1837.8,2005.07 U1.16
  Top Layer w25: R9.2 v1(1185,740) ; R10.1 1471.5,685 v1(1516.02,685)
  Bottom Layer w25: v1(1185,740) 1185,688.7 1238.7,635 1466.02,635 v1(1516.02,685) 1915.87,1084.84 1915.87,1959.87 1862.87,2012.87 v1(1830,2012.87)
NetR13_1: R13.1 R14.2 TP6.1 | length 192.6
  Top Layer w15: R13.1 R14.2 1998.5,2436.37 TP6.1
NetR16_2: R16.2 U1.12 | length 140.2
  Top Layer w15: R16.2 1880.2,2186.37 1840,2146.17 1840,2122.87 1855.43,2107.43 U1.12
NetR17_2: R17.2 U1.8 | length 146.1
  Top Layer w15: U1.8 2153.98,2081.84 2165,2092.87 2165,2176.37 R17.2
VCC: C23.1 D1.2 J3.3 U1.17 | length 751.3
  Top Layer w15: 1816.84,1980.24 1888.86,1980.24 U1.17
  Top Layer w20: J3.3 1651.26,2159.13 1630,2137.87 1630,1952.87 1660,1922.87 1730,1922.87 1745,1937.87 1770,1937.87 ; D1.2 1789.88,1852.98 1770,1872.87 1770,1937.87 ; 1816.84,1980.24 1772.37,1980.24 C23.1 1770,1937.87
VOUT: C1.1 C2.1 C3.1 C4.1 C5.1 C11.1 C12.2 C13.1 C14.1 C15.1 J2.1 Q1.5 Q1.6 Q1.7 Q1.8 Q1.9@1045,1232.52 Q2.5 Q2.6 Q2.7 Q2.8 Q2.9@1330,1232.52 R13.2 TP3.1 | length 2169.6
  Top Layer w15: v1(1825,2302.87) R13.2
  Bottom Layer w15: TP3.1 175,2457.5 255,2537.5 1732.5,2537.5 1825,2445 v1(1825,2302.87)
pads on no net: Q1.9@987.13,1182.91 Q1.9@987.13,1249.06 Q1.9@1045,1182.91 Q1.9@1045,1249.06 Q1.9@1102.87,1182.91 Q1.9@1102.87,1249.06 Q2.9@1272.13,1182.91 Q2.9@1272.13,1249.06 Q2.9@1330,1182.91 Q2.9@1330,1249.06 Q2.9@1387.87,1182.91 Q2.9@1387.87,1249.06 Q3.9@1267.13,722.91 Q3.9@1267.13,789.06 Q3.9@1325,722.91 Q3.9@1325,789.06 Q3.9@1382.87,722.91 Q3.9@1382.87,789.06 Q4.9@987.13,722.91 Q4.9@987.13,789.06 Q4.9@1045,722.91 Q4.9@1045,789.06 Q4.9@1102.87,722.91 Q4.9@1102.87,789.06 U1.1 U1.21@2005,2017.87

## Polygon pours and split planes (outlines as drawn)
NetL1_1 on Top Layer "NETL1_1_L01_P012" (solid, remove dead copper, pour order 12): 1355,516.21 1355,558.3 1387.67,590.97 1416.7,620 1565,620 2225,620 2600,620 2600,550 1535,550 1418.03,550 1385,516.97 1384.24,516.21 1355,516.21
GND on Top Layer "GND_L01_P020" (solid, remove dead copper, pour order 20): 0,2600 2595,2600 2595,5 2600,0 0,0
VOUT on Top Layer "VOUT_L01_P008" (solid, remove dead copper, pour order 8): 0,1200 435,1200 485,1150 850,1150 1140,1150 1150,1160 1150,1200 1150,1230 1165,1245 1175,1255 1195,1255 1220,1230 1220,1165 1220,1160 1230,1150 1245,1150 1435,1150 1445,1160 1445,1220 1445,1230 1465,1250 1470,1255 1480,1255 1483.54,1255 1505,1276.46 1505,1323.7 1505,1470 1505,1885 1505,2600 1420,2600 1380,2600 0,2600
NetC19_1 on Top Layer "NETC19_1_L01_P006" (solid, remove dead copper, pour order 6): 910,670 890,690 890,985 945,1040 945,1095 945,1115 955,1125 1045,1125 1090,1125 1100,1115 1100,1060 1110,1050 1130,1050 1135,1050 1140,1055 1170,1085 1205,1085 1215,1095 1212.27,1097.73 1214.53,1100 1215,1100 1215,1115 1225,1125 1375,1125 1385,1115 1385,1060 1395,1050 1425,1050 1430,1055 1460,1085 1465,1085 1503.07,1085 1503.54,1085.47 1505.47,1085.47 1515,1095 1516.02,1096.02 1516.02,1175 1516.02,1176.02 1535,1195 1665,1195 1675,1205 1675,1330 1695,1350 1790,1350 2140,1350 2600,1350 2600,620 2295,620 2060,620 1850,620 1565,620 1545,640 1545,700 1530,715 1510,735 1440,735 1425.39,720.39 1425.39,720 1425.39,675 1420.39,670 1420,670 1375,670 944.61,670
NetL1_1 on Top Layer "NETL1_1_L01_P002" (solid, remove dead copper, pour order 2): 1355,565 1355,475 1355,457.01 1362.01,450 1390,450 1480,450 1510,420 1510,400 1510,0 2600,0 2600,565
NetC6_1 on Top Layer "NETC6_1_L01_P000" (solid, remove dead copper, pour order 0): 0,435 895,435 905,435 940,400 960,380 1010,380 1310,380 1465,380 1470,380 1490,380 1490,0 0,0
GND on Bottom Layer "GND_L04_P014" (solid, remove dead copper, pour order 14): 0,2600 2595,2600 2600,2595 2600,0 0,0
GND on Signal Layer 2 "GND_L03_P016" (solid, remove dead copper, pour order 16): 0,2600 2600,2600 2600,0 0,0
GND on Signal Layer 1 "GND_L02_P018" (solid, remove dead copper, pour order 18): 0,2600 2600,2600 2600,0 0,0

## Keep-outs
Keep-Out Layer:
  lines w7: 0,0 0,2600 2600,2600 2600,0 0,0
  lines w10: 0,0 0,2600 2600,2600 2600,0 0,0
  text ".Layer_Name" at 577,-858.49 h60

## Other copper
Top Layer:
  pour cut-out: 1515,1333.54 1664.45,1333.54 1665,1332.99 1691.26,1359.25 2599.25,1359.25 2600,1360 2600,1395 1515,1395
  text ".Layer_Name" at 577,-858.49 h60
Bottom Layer:
  text ".Layer_Name" at 577,-858.49 h60

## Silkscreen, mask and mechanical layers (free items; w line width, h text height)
Top Overlay:
  lines w10: 1830,2390 1845,2390 1895,2340 ; 1695,2390 1905,2390 1905,2540 1905,2545 1700,2545 1695,2545 1695,2390
  text "1" at 1615,2295 h70
  text "2" at 1615,2220 h70
  text "3" at 1615,2140 h70
  text "." at 2130,1870 h100 r180
  text ".PRJ_Number" at 1850,75 h60
  text ".PCB_Rev" at 2450,75 h60
  text ".Layer_Name" at 577,-858.49 h60
Bottom Overlay:
  text ".Layer_Name" at 577,-858.49 h60
Top Paste:
  text ".Layer_Name" at 577,-858.49 h60
Bottom Paste:
  text ".Layer_Name" at 577,-858.49 h60
Top Solder:
  text ".Layer_Name" at 577,-858.49 h60
  text ".Layer_Name" at 577,-858.49 h60
Bottom Solder:
  text ".Layer_Name" at 577,-858.49 h60
Drill Guide:
  text ".Layer_Name" at 577,-858.49 h60
M1 Board Outline:
  the board outline again, w7
  text ".Layer_Name" at 577,-858.49 h60
M2 Board Dimensions:
  rectangle: 125,-400 500,-275
  rectangle: 0,-275 125,-150
  lines w7: 0,-275 1000,-275 ; 125,-400 125,-150 ; 250,-400 250,-150 ; 500,-400 500,-150 ; 750,-400 750,-150 ; 0,-400 0,-150 1000,-150 1000,-400 0,-400
  text ".Layer_Name" at 577,-858.49 h60
M3 3D STEP Top:
  text ".Layer_Name" at 577,-858.49 h60
M4 3D STEP Bottom:
  text ".Layer_Name" at 577,-858.49 h60
M5 Assembly Top:
  lines w10: -292,-930.17 6308,-930.17 ; -292,-726.83 6310,-726.83 ; -292,-523.5 -292,-1133.5 3713,-1133.5 6310,-1133.5 6310,-523.5 -291.5,-523.5 -291.5,-1133.5 1284,-1133.5 ; 2173,-1133.5 2173,-523.5 ; 3440,-726.83 3440,-523.5 ; 4280,-726.83 4280,-523.5 ; 4902,-1140 4902,-937.17
  text "PCB VIEWED FROM TOP SIDE" at -228.5,-655.67 h60
  text "BOARD #:" at 2248,-655.67 h60
  text ".PRJ_Number" at 2793.5,-655.67 h60
  text "REV:" at 3638,-655.67 h60
  text ".PCB_Rev" at 3929.5,-655.67 h60
  text "SVN REV:" at 4476,-655.67 h60
  text ".VersionControl_RevNumber" at 4982,-655.67 h60
  text "TID #:" at 2248,-859 h60
  text ".TID" at 2793.5,-859 h60
  text "PLOT NAME =" at -228.5,-1064.34 h60
  text ".plot_File_Name" at 577,-1064.34 h60
  text "GENERATED    :" at 2250,-1064.34 h60
  text ".Print_Date" at 3119.5,-1064.34 h60
  text ".Print_Time" at 3848.5,-1064.34 h60
  text "TEXAS INSTRUMENTS" at 5113,-1064.34 h60
M6 Assembly Bottom:
  lines w10: -292.5,-727.33 6309.5,-727.33 ; -290.5,-930.67 6309.5,-930.67 ; 1115.5,-1140.5 1115.5,-937.67 ; 1737.5,-727.33 1737.5,-524 ; 2577.5,-727.33 2577.5,-524 ; 3844.5,-1134 3844.5,-524 ; 4733.5,-1134 6309,-1134 6309,-524 -292.5,-524 -292.5,-1134 2304.5,-1134 6309.5,-1134 6309.5,-524
  text ".VersionControl_RevNumber" at 1035.5,-656.17 h60
  text "SVN REV:" at 1541.5,-656.17 h60
  text ".PCB_Rev" at 2088,-656.17 h60
  text "REV:" at 2379.5,-656.17 h60
  text ".PRJ_Number" at 3224,-656.17 h60
  text "BOARD #:" at 3769.5,-656.17 h60
  text "PCB VIEWED FROM BOTTOM SIDE" at 6246,-656.17 h60
  text ".TID" at 3224,-859.5 h60
  text "TID #:" at 3769.5,-859.5 h60
  text "TEXAS INSTRUMENTS" at 904.5,-1064.84 h60
  text ".Print_Time" at 2169,-1064.84 h60
  text ".Print_Date" at 2898,-1064.84 h60
  text "GENERATED    :" at 3767.5,-1064.84 h60
  text ".plot_File_Name" at 5440.5,-1064.84 h60
  text "PLOT NAME =" at 6246,-1064.84 h60
M9 Title Sheet:
  drawing of 57 lines, arcs and shapes, not listed
  text "1" at 739.84,8036.5 h70
  text "2" at 3235.5,8036.5 h70
  text "3" at 5724.84,8036.5 h70
  text "4" at 8231.51,8036.5 h70
  text "5" at 10730.5,8036.5 h70
  text "6" at 13235.5,8036.5 h70
  text "A" at -416.5,6893.5 h70
  text "A" at 14383.5,6893.5 h70
  text "B" at -416.5,4513.5 h70
  text "B" at 14383.5,4513.5 h70
  text "C" at -416.5,2138.5 h70
  text "C" at 14383.5,2138.5 h70
  text "PROJECT TITLE:" at 11343.5,277.5 h45
  text ".PRJ_Title" at 11393.5,144.17 h70
  text "DESIGNED FOR:" at 11343.5,-23.5 h45
  text ".PRJ_Customer" at 11393.5,-163.5 h70
  text "D" at -416.5,-231.5 h70
  text "D" at 14383.5,-231.5 h70
  text "FILE NAME:" at 11343.5,-323.5 h45
  text ".PCB_File_Name_No_Path" at 11393.5,-443.5 h70
  text "Texas Instruments (TI) and/or its licensors do not warrant the accuracy or completeness of this specification" at 6374,-605.34 h45
  text "ENGINEER:" at 11343.5,-613.5 h45
  text "LAYOUT BY:" at 12848.5,-613.5 h45
  text "or any information contained therein. TI and/or its licensors do not warrant that this design will meet" at 6329.01,-718 h45
  text ".PRJ_Engineer" at 11393.5,-768.49 h70
  text ".PCB_Layout" at 12899,-768.49 h70
  text "the specifications, will be suitable for your application or fit for any particular purpose, or will operate in" at 6329.01,-830.67 h45
  text ".Layer_Name" at 577,-858.49 h60
  text "ALTIUM DESIGNER VERSION:" at 12848.5,-923.5 h45
  text "an implementation. TI and/or its licensors do not warrant that the design is production worthy. You should" at 6329.01,-943.33 h45
  text "completely validate and test your design implementation to confirm the system functionality for your application." at 6374,-1056 h45
  text ".print_Scale" at 11393.5,-1056.83 h70
  text ".Application_BuildNumber" at 12899,-1056.83 h70
  text "1" at 739.84,-1263.5 h70
  text "2" at 3235.5,-1263.5 h70
  text "3" at 5724.84,-1263.5 h70
  text "4" at 8231.51,-1263.5 h70
  text "5" at 10730.5,-1263.5 h70
  text "6" at 13235.5,-1263.5 h70
M10 Fab Notes:
  drawing of 173 lines, arcs and shapes, not listed
  text "DESIGN INFORMATION" at 12377.02,6201 h60
  text "MIN. TRACK WIDTH:" at 11732.46,6021 h60
  text "8" at 12828.7,6021 h60
  text "MIL" at 12983.46,6021 h60
  text "MIN. CLEARANCE:" at 11732.46,5889 h60
  text "0.2" at 12768.7,5889 h60
  text "mm" at 12983.46,5889 h60
  text "MIN. VIA PAD SIZE:" at 11732.46,5757 h60
  text "24" at 12798.71,5757 h60
  text "MIL" at 12983.46,5757 h60
  text "0.05mm (2MIL)" at 12427.46,5615.29 h60
  text "MINIMUM ANNULAR RING" at 11403.23,5611 h60
  text "EXTERNAL" at 13135.46,5611 h60
  text "PER" at 11603.23,5493 h60
  text "IPC-D-275 CLASS 2 LEVEL C" at 11823.23,5493 h60
  text "MIL, HOLES" at 13311.46,5380.71 h60
  text "+/-" at 12919,5380 h60
  text "+/-" at 13773,5380 h60
  text "REGISTRATION TOLERANCES:" at 11403.23,5375 h60
  text "METAL" at 12603,5375 h60
  text "5" at 13179.2,5375 h60
  text "3" at 14012.2,5375 h60
  text "MIL" at 14128.46,5375 h60
  text "+/-" at 13773,5262 h60
  text "HOLE SIZE TOLERANCE (UNLESS OTHERWISE SPECIFIED):" at 11403.23,5257 h60
  text "3" at 14012.2,5257 h60
  text "MIL" at 14128.46,5257 h60
  text "MATERIAL:" at 11328.46,5047.54 h60
  text "FR-4 High Tg" at 12314.9,4907.21 h60
  text "FR-408" at 11749.46,4898.64 h60
  text "OTHER" at 13237.46,4898.64 h60
  text "X" at 12160,4895 h60
  text "62 MIL (1.6mm) +/-10%" at 12069.56,4735.92 h60
  text "THICKNESS:" at 11403.23,4731.64 h60
  text "X" at 11941.4,4731.64 h60
  text "OTHER" at 13354.46,4731.64 h60
  text "TOLERANCE:" at 11403.23,4573.64 h60
  text "X" at 12242.53,4573.64 h60
  text "ANSI IPC-6012 TYPE 3 CLASS 2" at 12429.48,4573.64 h60
  text "OTHER +/-" at 12429.46,4417.64 h60
  text "BOW & TWIST:" at 11403.23,4260.64 h60
  text "X" at 12242.53,4260.64 h60
  text "ANSI IPC-6012 TYPE 3 CLASS 2" at 12429.48,4260.64 h60
  text "OTHER +/-" at 12429.46,4102.13 h60
  text "DRILLING:" at 11328.46,3963.64 h60
  text "REFERENCE:" at 11403.23,3846.64 h60
  text "X" at 12051.46,3846.64 h60
  text "AS SHOWN" at 12238.46,3846.64 h60
  text "X" at 12952.46,3846.64 h60
  text "NC_DRILL FILES" at 13089.46,3846.64 h60
  text "PTH COPPER THICKNESS:" at 11403.23,3688.64 h60
  text "X" at 12533.46,3688.64 h60
  text "20-30 um" at 12670.46,3688.64 h60
  text "OTHER" at 13387.46,3688.64 h60
  text "BOARD FINISH:" at 11328.46,3529.64 h60
  text "SILKSCREEN:" at 11483.68,3411.64 h60
  text "X" at 12432.46,3411.64 h60
  text "TOP" at 12558.46,3411.64 h60
  text "BOTTOM" at 13069.46,3411.64 h60
  text "SILKSCREEN COLOR:" at 11483.68,3244.64 h60
  text "X" at 12431.42,3244.64 h60
  text "WHITE" at 12558.46,3244.64 h60
  text "OTHER" at 13069.46,3244.64 h60
  text "X" at 12562.42,3085.44 h60
  text "GREEN" at 12689.46,3085.44 h60
  text "OTHER" at 13307.46,3085.44 h60
  text "SOLDER RESIST COLOR:" at 11483.68,3074.64 h60
  text "X" at 12562.42,2915.44 h60
  text "MATTE" at 12689.46,2915.44 h60
  text "SEMI-GLOSS" at 13307,2914.8 h60
  text "IMMERSION GOLD (ENIG)" at 12389.46,2726.92 h60
  text "ENEPIG" at 13727,2723.64 h60
  text "SURFACE FINISH:" at 11328.46,2722.64 h60
  text "X" at 12202.51,2722.64 h60
  text "IMM. TIN/SILVER OR EQUIV" at 11658,2565.64 h60
  text "OTHER" at 13089.46,2565.64 h60
  text "X" at 12200,2390 h60
  text "ARRAY/PANEL:" at 11328.46,2386.64 h60
  text "CUT AND TRIM PER M1 BOARD OUTLINE" at 12389.46,2382.35 h60
  text "N.C. ROUTE" at 12389.46,2230.64 h60
  text "V. SCORE" at 13255.46,2230.64 h60
  text "CERTIFICATION:" at 11328.46,2093.64 h60
  text "MATERIALS AND WORKMANSHIP FOR ALL PCBS" at 12053.46,2093.64 h60
  text "TO MEET OR EXCEED THE REQUIREMENTS OF:" at 12053.46,1995.64 h60
  text "X" at 11679.96,1859.13 h60
  text "ANSI IPC-A-600F CLASS ->" at 11818.96,1859.13 h60
  text "X" at 13458.02,1859.13 h60
  text "2" at 13576.96,1859.14 h60
  text "1" at 13261.96,1857.64 h60
  text "3" at 13930.96,1857.64 h60
  text "X" at 12494.02,1699.64 h60
  text "RoHS" at 12630.96,1699.64 h60
  text "OTHER" at 13275.36,1699.64 h60
  text "PER ORDER" at 13672.42,1699.64 h60
  text "ALL BOARDS MUST MEET OR EXCEED UL94-V0 REQUIREMENTS." at 11356,1534 h60
  text "PCB MUST BEAR THE UL94V-0 UL REGISTERED MATERIAL ID NUMBER" at 11356,1414 h60
  text "ADDITIONAL REQUIREMENTS:" at 11328.46,1240.64 h60
  text "MICROSECTION:" at 11403.23,1125.64 h60
  text "YES" at 12308.96,1125.64 h60
  text "REQUIRED" at 13170.46,969.49 h60
  text "BARE BOARD ELEC. TEST:" at 11403.23,966.64 h60
  text "NONE" at 12708.96,966.64 h60
  text "X" at 13043.46,966.64 h60
  text "PER ORDER" at 13762.46,966.64 h60
  text ".Layer_Name" at 577,-858.49 h60
M11 Gerber Information:
  lines w10: -292,-930.17 6308,-930.17 ; -292,-726.83 6310,-726.83 ; -292,-523.5 -292,-1133.5 3713,-1133.5 6310,-1133.5 6310,-523.5 -291.5,-523.5 -291.5,-1133.5 1284,-1133.5 ; 2173,-1133.5 2173,-523.5 ; 3440,-726.83 3440,-523.5 ; 4280,-726.83 4280,-523.5 ; 4902,-1140 4902,-937.17
  text "ALL ARTWORK VIEWED FROM TOP SIDE" at -228.5,-655.67 h60
  text "BOARD #:" at 2248,-655.67 h60
  text ".PRJ_Number" at 2793.5,-655.67 h60
  text "REV:" at 3638,-655.67 h60
  text ".PCB_Rev" at 3929.5,-655.67 h60
  text "SVN REV:" at 4476,-655.67 h60
  text ".VersionControl_RevNumber" at 4982,-655.67 h60
  text "LAYER NAME =" at -228.5,-858.49 h60
  text "TID #:" at 2248,-859 h60
  text ".TID" at 2793.5,-859 h60
  text "PLOT NAME =" at -228.5,-1064.34 h60
  text ".plot_File_Name" at 577,-1064.34 h60
  text "GENERATED    :" at 2250,-1064.34 h60
  text ".Print_Date" at 3119.5,-1064.34 h60
  text ".Print_Time" at 3848.5,-1064.34 h60
  text "TEXAS INSTRUMENTS" at 5113,-1064.34 h60
M12 Stackup:
  drawing of 295 lines, arcs and shapes, not listed
  text "Layer" at 9798.08,7830 h60
  text "Name" at 10207.99,7830 h60
  text "Material" at 11147.73,7830 h60
  text "Thickness" at 12007.5,7830 h60
  text "Constant" at 12657.33,7830 h60
  text "Board Layer Stack" at 13227.19,7830 h60
  text "1" at 9798.08,7710 h60
  text "Top Overlay" at 10207.99,7710 h60
  text "2" at 9798.08,7590 h60
  text "Top Solder" at 10207.99,7590 h60
  text "Solder Resist" at 11147.73,7590 h60
  text "0.40mil" at 12007.5,7590 h60
  text "3.5" at 12657.33,7590 h60
  text "3" at 9798.08,7470 h60
  text "Top Layer" at 10207.99,7470 h60
  text "Copper" at 11147.73,7470 h60
  text "2.80mil" at 12007.5,7470 h60
  text "4" at 9798.08,7350 h60
  text "Dielectric1" at 10207.99,7350 h60
  text "FR-4" at 11147.73,7350 h60
  text "59.20mil" at 12007.5,7350 h60
  text "4.8" at 12657.33,7350 h60
  text "5" at 9798.08,7230 h60
  text "Signal Layer 1" at 10207.99,7230 h60
  text "Copper" at 11147.73,7230 h60
  text "2.80mil" at 12007.5,7230 h60
  text "6" at 9798.08,7110 h60
  text "Dielectric 3" at 10207.99,7110 h60
  text "5.00mil" at 12007.5,7110 h60
  text "4.2" at 12657.33,7110 h60
  text "7" at 9798.08,6990 h60
  text "Signal Layer 2" at 10207.99,6990 h60
  text "Copper" at 11147.73,6990 h60
  text "2.80mil" at 12007.5,6990 h60
  text "8" at 9798.08,6870 h60
  text "Dielectric 2" at 10207.99,6870 h60
  text "10.00mil" at 12007.5,6870 h60
  text "4.2" at 12657.33,6870 h60
  text "9" at 9798.08,6750 h60
  text "Bottom Layer" at 10207.99,6750 h60
  text "Copper" at 11147.73,6750 h60
  text "2.80mil" at 12007.5,6750 h60
  text "10" at 9798.08,6630 h60
  text "Bottom Solder" at 10207.99,6630 h60
  text "Solder Resist" at 11147.73,6630 h60
  text "0.40mil" at 12007.5,6630 h60
  text "3.5" at 12657.33,6630 h60
  text "11" at 9798.08,6510 h60
  text "Bottom Overlay" at 10207.99,6510 h60
  text ".Layer_Name" at 577,-858.49 h60
M13 Component Bodies Top:
  text ".Layer_Name" at 577,-858.49 h60
M14 Component Bodies Bottom:
  text ".Layer_Name" at 577,-858.49 h60
M15 Courtyards Top:
  text ".Layer_Name" at 577,-858.49 h60
M16 Courtyards Bottom:
  text ".Layer_Name" at 577,-858.49 h60
Drill Drawing:
  circle w10: c3823.72,2286.96 r27.63
  lines w10: 3796.09,1775.87 3809.9,1775.87 3823.72,1762.06 3837.53,1775.87 3851.34,1775.87 3837.53,1789.68 3851.34,1803.5 3837.53,1803.5 3823.72,1817.31 3809.9,1803.5 3796.09,1803.5 3809.9,1789.68 3796.09,1775.87 ; 3796.09,1886.38 3823.72,1900.19 3851.34,1886.38 3837.53,1914 3851.34,1941.63 3823.72,1927.82 3796.09,1941.63 3809.9,1914 3796.09,1886.38 ; 3796.09,2065.95 3851.34,2065.95 3823.72,2010.7 3796.09,2065.95 ; 3796.09,2135.02 3796.09,2148.83 3809.9,2162.64 3796.09,2176.46 3796.09,2190.27 3809.9,2190.27 3823.72,2176.46 3837.53,2190.27 3851.34,2190.27 3851.34,2176.46 3837.53,2162.64 3851.34,2148.83 3851.34,2135.02 3837.53,2135.02 3823.72,2148.83 3809.9,2135.02 3796.09,2135.02 ; 3796.09,2397.47 3809.9,2397.47 3809.9,2383.66 3837.53,2383.66 3837.53,2397.47 3851.34,2397.47 3851.34,2425.1 3837.53,2425.1 3837.53,2438.91 3809.9,2438.91 3809.9,2425.1 3796.09,2425.1 3796.09,2397.47
  lines w12: 3746,1724.76 6977.49,1724.76 ; 3746,2470.68 6977.49,2470.68 ; 4083.86,1600.44 4083.86,2595 ; 4415.86,1600.44 4415.86,2595 ; 5052.43,1600.44 5052.43,2595 ; 5311.57,1600.44 5311.57,2595 ; 5686.72,1600.44 5686.72,2595 ; 6411.05,1600.44 6411.05,2595 ; 3746,1600.44 6977.49,1600.44 6977.49,2595 3746,2595 3746,1600.44
  text "Symbol" at 3820.59,2507.98 h72
  text "Quantity" at 4121.16,2507.98 h72
  text "Finished Hole Size" at 4453.16,2507.98 h72
  text "Plated" at 5089.72,2507.98 h72
  text "Hole Type" at 5348.86,2507.98 h72
  text "Drill Layer Pair" at 5724.02,2507.98 h72
  text "Hole Tolerance" at 6448.35,2507.98 h72
  text "15" at 4121.16,2383.66 h60
  text "7.87mil (0.200mm)" at 4453.16,2383.66 h60
  text "PTH" at 5089.72,2383.66 h60
  text "Round" at 5348.86,2383.66 h60
  text "Top Layer - Bottom Layer" at 5724.02,2383.66 h60
  text "75" at 4121.16,2259.34 h60
  text "16.00mil (0.406mm)" at 4453.16,2259.34 h60
  text "PTH" at 5089.72,2259.34 h60
  text "Round" at 5348.86,2259.34 h60
  text "Top Layer - Bottom Layer" at 5724.02,2259.34 h60
  text "3" at 4121.16,2135.02 h60
  text "31.89mil (0.810mm)" at 4453.16,2135.02 h60
  text "PTH" at 5089.72,2135.02 h60
  text "Round" at 5348.86,2135.02 h60
  text "Top Layer - Bottom Layer" at 5724.02,2135.02 h60
  text "+/-1.97mil" at 6448.35,2135.02 h60
  text "8" at 4121.16,2010.7 h60
  text "33.46mil (0.850mm)" at 4453.16,2010.7 h60
  text "PTH" at 5089.72,2010.7 h60
  text "Round" at 5348.86,2010.7 h60
  text "Top Layer - Bottom Layer" at 5724.02,2010.7 h60
  text "4" at 4121.16,1886.38 h60
  text "49.21mil (1.250mm)" at 4453.16,1886.38 h60
  text "PTH" at 5089.72,1886.38 h60
  text "Round" at 5348.86,1886.38 h60
  text "Top Layer - Bottom Layer" at 5724.02,1886.38 h60
  text "7" at 4121.16,1762.06 h60
  text "63.00mil (1.600mm)" at 4453.16,1762.06 h60
  text "PTH" at 5089.72,1762.06 h60
  text "Round" at 5348.86,1762.06 h60
  text "Top Layer - Bottom Layer" at 5724.02,1762.06 h60
  text "112 Total" at 4121.16,1637.74 h60
  text ".Layer_Name" at 577,-858.49 h60

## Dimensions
0,0 to 2600,0 on M2 Board Dimensions
0,0 to 0,2600 on M2 Board Dimensions
0,-400 to 1000,-400 on M2 Board Dimensions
